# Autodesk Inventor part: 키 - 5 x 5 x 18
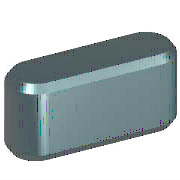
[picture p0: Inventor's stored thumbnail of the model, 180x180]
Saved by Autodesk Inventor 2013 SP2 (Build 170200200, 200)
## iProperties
Created: 2012-02
Part Number: 키 - 5 x 5 x 18
Material: 강철, 연강
Description: 키 및 해당 키홈
Document SubType Name: Modeling
Standard: KS B 1311
Designer: mduedu
Standards Organization: KS
Language: ko-KR
Size Designation: 5 x 5 x 18
Categories: <MemberInstance><Categories><Category DisplayName="샤프트 부품" InternalName="7f7aeb1f-a693-4053-b835-cee3144e0d98" Mnemonic="SHFT"><Category DisplayName="키" Interna
Density: 1 g/cm^3
IsCustomPart: 1
Author: mduedu
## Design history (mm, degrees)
workplane "Work Plane1"
workplane "Work Plane2"
sketch "스케치1"
  geometry: L1 (2.5, 2.5)-(15.5, 2.5); L2 (15.5, -2.5)-(2.5, -2.5); L3 (0, 9.4)-(0, -7.4) reference; L4 (-5, 0)-(30, 0) reference; L5 (18, 0)-(18, 7); A1 r 2.5 centre (2.5, 0) between (2.5, 2.5) and (2.5, -2.5); A2 r 2.5 centre (15.5, 0) between (15.5, -2.5) and (15.5, 2.5)
  constraints: 6 end point, 5 point on circle, 4 tangent, 3 point on line, 2 centre point, 1 horizontal, 1 parallel, 1 perpendicular
  dimensions: "d0" = 2.5 radius of A1 (= 0.5 x PB); "d13" = 2.5 radius of A2 (= 0.5 x PB); "d14" = 18 distance between parallel lines of L5 L3 (= NLG)
extrude "본체1" new body sketch "스케치1" taper "d3" = 0 deg; stored distance "d4" = 10
workplane "Work Plane3"
body "Solid1"
chamfer "모따기1" distance "d8" = 0.4 (= PHH); stored, may be unused: second distance "d9" = 0.4 (= PHH), angle "d15" = 45 deg
other parameters: "d1" = -3 (= -PNT), "d2" = 2 (= PH - PNT), "NLG" = 18 [user parameter; used in 3 equation terms], "PB" = 5 [user parameter; used in 2 equation terms], "PNT" = 3 [user parameter; used in 2 equation terms], "PH" = 5 [user parameter; used in 1 equation term], "PHH" = 0.4 [user parameter; used in 2 equation terms], "d10" = 0, "d16" = 0, "d17" = 0, "d18" = 0, "WDMIN" = 12 [user parameter], "PLB2" = 18 (= NLG) [user parameter], "WDMAX" = 17 [user parameter], "PLB1" = 18 (= NLG) [user parameter], "RR" = 0.16 [user parameter], "PUEB" = 2.3 [user parameter]
